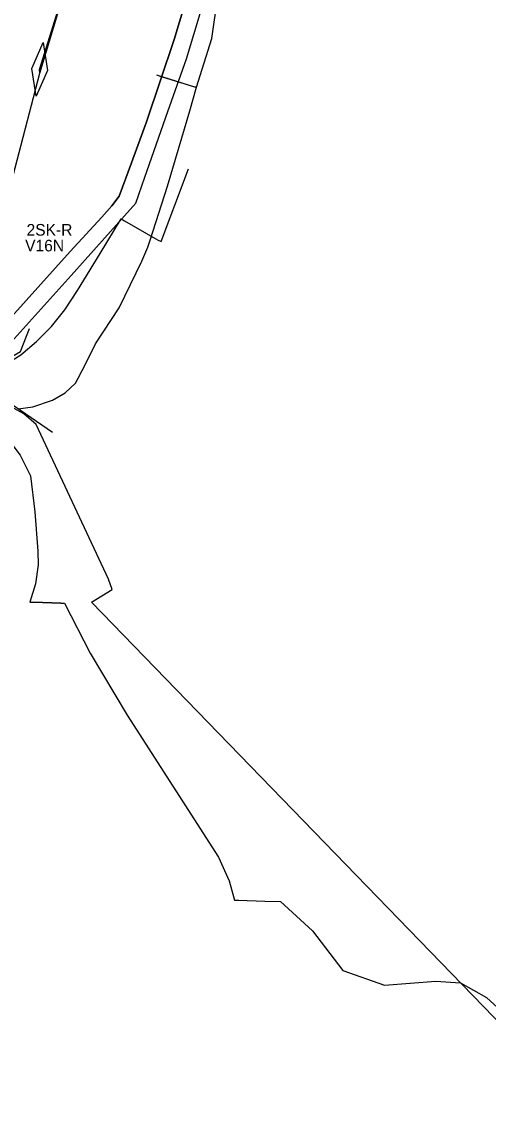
# Model space of a CAD drawing. Extents: x -748507 to -687366, y -1057342 to -1024924.
# Drawn here: x -743248.5 to -743188.4, y -1034654.5 to -1034515.3 of the extents above; entities that cross this region are included whole.
import ezdxf

# ---------------------------------------------------------------- set-up
doc = ezdxf.new("R2010")
doc.units = 0
for name, color, linetype in [('DK + TKK - SŽDC', 7, 'Continuous'), ('PRE - NN', 7, 'Continuous'), ('PRE - OK', 7, 'Continuous'), ('PRE - VN', 7, 'Continuous'), ('Sděl MK - SŽDC', 7, 'Continuous'), ('STL - PRAŽSKÁ PLYNÁRENSKÁ', 7, 'Continuous'), ('SčVK_kanalizace', 7, 'Continuous'), ('Telefonica O2', 7, 'Continuous')]:
    doc.layers.add(name, color=color, linetype=linetype)

msp = doc.modelspace()

# ---------------------------------------------------------------- linework, layer by layer
at = {"layer": 'DK + TKK - SŽDC'}
msp.add_lwpolyline([(-743251.53, -1034542.4), (-743246.18, -1034521.96), (-743241.03, -1034504.8), (-743239.25, -1034495.65), (-743233.91, -1034484.65), (-743234.75, -1034484.02), (-743235.66, -1034483.63)], dxfattribs=at)
at = {"layer": 'PRE - NN'}
msp.add_lwpolyline([(-743275.12, -1034555.03), (-743270.82, -1034556.83), (-743268.97, -1034557.74), (-743256.76, -1034560.46), (-743254.53, -1034560.63), (-743251.44, -1034558.36), (-743242.16, -1034548.04), (-743233.82, -1034538.72), (-743232.65, -1034535.37), (-743229.68, -1034526.89), (-743227.3, -1034520.1), (-743220.12, -1034496.25), (-743217.83, -1034487.97), (-743213.66, -1034474.75), (-743212.88, -1034472.84), (-743209.68, -1034465.05), (-743204.81, -1034455.36), (-743200.32, -1034446.8), (-743198.79, -1034444.04), (-743191.74, -1034431.05), (-743189.38, -1034426.93), (-743187.05, -1034422.46)], dxfattribs=at)
at = {"layer": 'PRE - OK'}
msp.add_lwpolyline([(-743226.7, -1034510.28), (-743228.86, -1034517.6), (-743232.45, -1034528.21), (-743234.35, -1034533.49), (-743235.96, -1034537.8), (-743236.89, -1034539.06), (-743238.2, -1034540.49), (-743242.25, -1034544.94), (-743251.76, -1034555.48)], dxfattribs=at)
at = {"layer": 'PRE - VN'}
msp.add_lwpolyline([(-743251.76, -1034555.48), (-743242.25, -1034544.94), (-743238.2, -1034540.49), (-743236.89, -1034539.06), (-743235.96, -1034537.8), (-743234.35, -1034533.49), (-743232.45, -1034528.21), (-743228.86, -1034517.6), (-743226.7, -1034510.28)], dxfattribs=at)
at = {"layer": 'Sděl MK - SŽDC'}
for points in [[(-743268.89, -1034611.84), (-743268.78, -1034607.9), (-743267.19, -1034604.4), (-743264.3, -1034591.83), (-743262.02, -1034583.38), (-743259.96, -1034574.09), (-743257.39, -1034564.51), (-743253.16, -1034548.54), (-743252.58, -1034546.35), (-743251.82, -1034543.49), (-743251.53, -1034542.4), (-743246.18, -1034521.96), (-743246.2, -1034521.46), (-743241.03, -1034504.8)], [(-743246.66, -1034524.93), (-743247.19, -1034521.33), (-743245.74, -1034517.99), (-743245.21, -1034521.59), (-743246.66, -1034524.93)]]:
    msp.add_lwpolyline(points, dxfattribs=at)
at = {"layer": 'STL - PRAŽSKÁ PLYNÁRENSKÁ'}
for p, q in [((-743226.19, -1034523.74), (-743231.09, -1034522.21)), ((-743233.05, -1034546.19), (-743232.26, -1034544.37))]:
    msp.add_line(p, q, dxfattribs=at)
for points in [[(-743248.99, -1034565.21), (-743247.06, -1034564.95), (-743244.56, -1034564.09), (-743242.92, -1034563.14), (-743241.57, -1034561.9), (-743241.25, -1034561.27), (-743240.23, -1034559.27), (-743238.99, -1034556.82), (-743235.96, -1034552.21), (-743233.05, -1034546.19), (-743232.26, -1034544.37), (-743232.14, -1034543.98), (-743231.97, -1034543.47), (-743229.74, -1034536.53), (-743226.84, -1034526.82), (-743226, -1034523.75), (-743224.01, -1034517.46), (-743223.24, -1034512.06)], [(-743226, -1034523.75), (-743226.19, -1034523.74), (-743230.5, -1034522.4), (-743231.09, -1034522.21)]]:
    msp.add_lwpolyline(points, dxfattribs=at)
at = {"layer": 'SčVK_kanalizace'}
msp.add_lwpolyline([(-743253.64, -1034561.99), (-743244.56, -1034568.23)], dxfattribs=at)
at = {"layer": 'Telefonica O2'}
for points in [[(-743251.64, -1034559.66), (-743250.83, -1034559.58), (-743250.26, -1034559.27), (-743248.64, -1034558.25), (-743246.62, -1034556.55), (-743244.69, -1034554.61), (-743242.96, -1034552.47), (-743241.34, -1034549.95), (-743238.41, -1034545.19), (-743235.68, -1034540.73), (-743235.26, -1034541), (-743231, -1034543.42), (-743230.55, -1034543.64), (-743227.02, -1034534.29)], [(-743295.34, -1034569.86), (-743292.06, -1034556.8), (-743289.18, -1034554.76), (-743269.67, -1034558.14), (-743256.82, -1034560.82), (-743253.14, -1034560.42), (-743248.68, -1034557.84), (-743247.49, -1034554.86)], [(-743237.34, -1034587.18), (-743246.67, -1034567.23), (-743248.26, -1034565.84), (-743251.53, -1034564.06), (-743255.45, -1034563.21), (-743258.18, -1034563.91), (-743268.61, -1034561.37), (-743270.89, -1034561.08), (-743274.61, -1034562.22), (-743276.9, -1034563.81), (-743278.44, -1034565.45), (-743279.78, -1034568.77), (-743284.99, -1034587.1), (-743290.28, -1034604.7), (-743294.12, -1034615.45), (-743298.34, -1034624.19), (-743301.04, -1034629.14), (-743314.56, -1034657.86), (-743319.49, -1034663.3), (-743319.01, -1034664.96), (-743320.86, -1034665.49), (-743329.4, -1034675.81), (-743343.26, -1034696.57), (-743359.5, -1034716.04)], [(-743256.47, -1034560.3), (-743253.46, -1034566.39), (-743250.43, -1034568.9), (-743248.72, -1034571.21), (-743247.36, -1034573.84)], [(-743247.36, -1034573.84), (-743246.83, -1034578.5), (-743246.43, -1034583.57), (-743246.4, -1034585.33), (-743246.73, -1034587.77), (-743247.47, -1034590.12), (-743246.99, -1034590.14), (-743243.49, -1034590.26), (-743243.01, -1034590.27), (-743239.71, -1034596.72), (-743234.94, -1034604.7), (-743223.15, -1034623.02), (-743221.77, -1034626.04), (-743221.09, -1034628.54), (-743220.59, -1034628.56), (-743217.17, -1034628.68), (-743215.15, -1034628.73), (-743211.03, -1034632.51), (-743207.13, -1034637.64), (-743201.76, -1034639.53), (-743195.16, -1034638.98), (-743191.98, -1034639.19), (-743188.64, -1034641.08), (-743186.71, -1034642.88)], [(-743239.54, -1034590.13), (-743236.84, -1034588.52), (-743237.34, -1034587.18)], [(-743243.49, -1034590.26), (-743246.99, -1034590.14)], [(-743239.54, -1034590.13), (-743179.48, -1034652.1)]]:
    msp.add_lwpolyline(points, dxfattribs=at)

# ---------------------------------------------------------------- texts
at = {"layer": 'DK + TKK - SŽDC'}
for s, p in [('2SK-R', (-743247.89, -1034542.89)), ('V16N', (-743248.07, -1034544.92))]:
    msp.add_text(s, height=1.5, dxfattribs=at).set_placement(p)

doc.saveas('drawing.dxf')
